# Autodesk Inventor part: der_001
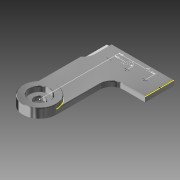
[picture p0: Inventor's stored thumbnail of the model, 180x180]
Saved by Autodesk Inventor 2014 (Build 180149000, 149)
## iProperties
Created: 2007-10
Part Number: der_001
Document SubType Name: Modeling
Designer: hassen
Density: 1 g/cm^3
Material: Generic
Appearance: No Tint
Author: hassen
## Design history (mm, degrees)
sketch "Sketch1"
  geometry: L1 (0, 35)-(91, 35); L2 (0, -35)-(175, -35); L3 (175, -35)-(175, 105); L4 (175, 105)-(115, 105); L5 (115, 105)-(115, 59); A1 r 35 centre (0, 0) between (0, 35) and (0, -35); A2 r 24 centre (91, 59) between (91, 35) and (115, 59); 2 further points
  constraints: 10 end point, 4 point on circle, 2 centre point, 2 point on line, 2 tangent, 1 coincident
  dimensions: "d1" = 35 radius of A1; "d2" = 175 distance of L2.start L2.end (= 5 x d1); "d3" = 60 distance of L3.end L4.end; "d4" = 140 distance between parallel lines of L2 L4; "d5" = 70 distance of L4.end point (115, 35) (derived); "d37" = 24 radius of A2
extrude "Extrusion1" new body sketch "Sketch1" distance "d6" = 10.5 (= 0.3 x d1); taper "d7" = 0 deg
sketch "Sketch2"
  geometry: C1 r 35 at (0, 0); A1 r 35 centre (0, 0) between (0, -35) and (0, 35) reference
  constraints: 1 centre point, 1 coincident
  dimensions: "d38" = 70 diameter of C1 (= 2 x d1)
extrude "Extrusion2" join sketch "Sketch2" distance "d8" = 8.75 (= 0.25 x d1); taper "d9" = 0 deg
hole "Hole1" diameter "d12" = 21 (= 0.6 x d1); stored, may be unused: countersink angle "d16" = 90 deg, drill point angle "d18" = 118 deg; dims "d10" = 10, "d11" = 10, "d13" = 6, "d14" = 42 (= 1.2 x d1), "d15" = 10.5 (= 0.3 x d1), "d17" = 8
sketch "Sketch4"
  geometry: L1 (-175, 105)-(-175, -35) reference; L2 (-175, -35)-(0, -35) reference; L3 (-175, -25)-(-140, -25); A1 r 25 centre (-140, -50) between (-120, -35) and (-140, -25)
  constraints: 2 end point, 2 point on circle, 2 point on line, 1 centre point, 1 tangent
  dimensions: "d31" = 10 distance between parallel lines of L2 L3; "d32" = 25 radius of A1; "d33" = 35 distance of L3.start L3.end; "d34" = 15 distance from line of A1.centre L2 (derived)
extrude "Extrusion3" cut sketch "Sketch4" distance "d35" = 5.25 (= 0.5 x d6); taper "d36" = 0 deg
sketch "Sketch3"
  geometry: L1 (-115, 105)-(-175, 105) reference; A1 r 35 centre (0, 0) between (0, 35) and (0, -35) reference; 5 further points
  constraints: 3 vertical alignment, 2 midpoint, 1 horizontal alignment
  dimensions: "d19" = 75 vertical distance of A1.centre point (-145, 75); "d20" = 37.5 vertical distance of A1.centre point (-145, 37.5) (= 0.5 x d19)
chamfer "Chamfer1" distance "d28" = 1; stored, may be unused: second distance "d29" = 2, angle "d30" = 45 deg
body "Solid1"
